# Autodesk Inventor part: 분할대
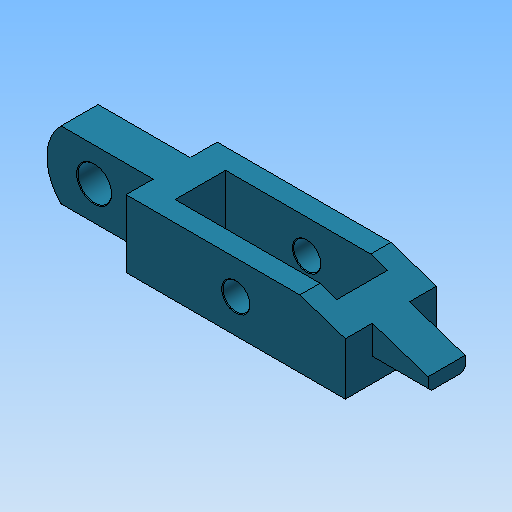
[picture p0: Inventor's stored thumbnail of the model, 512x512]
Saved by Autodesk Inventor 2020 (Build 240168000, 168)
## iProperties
Created: 2016-11
Part Number: 분할대
Material: 강철, 연강
Document SubType Name: Modeling
Designer: mduedu
Density: 1 g/cm^3
Appearance: 터키옥색
Author: mduedu
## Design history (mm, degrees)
sketch "스케치1"
  geometry: L1 (32.5, 13.5)-(-32.5, 13.5); L2 (-32.5, 13.5)-(-32.5, -13.5); L3 (-32.5, -13.5)-(32.5, -13.5); L4 (32.5, -13.5)-(32.5, 13.5); L5 (24, 7.5)-(-24, 7.5); L6 (-24, 7.5)-(-24, -7.5); L7 (-24, -7.5)-(24, -7.5); L8 (24, -7.5)-(24, 7.5); L9 (24, 0)-(-24, 0); L10 (0, -13.5)-(0, 13.5); 4 further points
  constraints: 20 end point, 7 midpoint, 4 parallel, 2 coincident, 2 horizontal, 2 perpendicular, 1 horizontal alignment
  dimensions: "d0" = 15 distance of L5.end L6.end; "d2" = 27 distance between parallel lines of L1 L3; "d3" = 48 distance of L5.start L5.end; "d4" = 65 distance of L1.start L1.end
extrude "돌출1" new body sketch "스케치1" distance "d5" = 20; taper "d6" = 0 deg
sketch "스케치2"
  geometry: L1 (0, 0)-(65, 0) reference; L2 (65, 0)-(65, 20) reference; L3 (0, 20)-(65, 20) reference; L4 (0, 0)-(0, 20) reference; L5 (32.5, 0)-(32.5, 20); C1 r 4 at (32.5, 10)
  constraints: 2 end point, 2 midpoint, 1 centre point
  dimensions: "d7" = 8 diameter of C1
extrude "돌출2" cut sketch "스케치2" extent not by distance; stored distance "d8" = 20; taper "d9" = 0 deg
chamfer "모따기1" distance "d10" = 0.2; stored, may be unused: second distance "d11" = 2, angle "d12" = 45 deg
sketch "스케치3"
  geometry: L1 (-32.5, 0)-(-32.5, 20) reference; L2 (-32.5, 20)-(-59.798, 20); L3 (-64, 20)-(-64, 0); L4 (-64, 0)-(-59.798, 0); L5 (-32.5, 0)-(-32.5, 20); L6 (-59.798, 20)-(-64, 20); L7 (-59.798, 0)-(-32.5, 0); C1 r 4.2 at (0, 10) reference; C2 r 5 at (-50, 10); A1 r 14 centre (-50, 10) between (-59.798, 20) and (-59.798, 0); 1 further point
  constraints: 12 end point, 5 parallel, 2 centre point, 2 horizontal, 2 perpendicular, 2 point on circle, 1 coincident, 1 horizontal alignment, 1 tangent
  dimensions: "d13" = 64 distance from line of L3 C1.centre; "d14" = 14 radius of A1; "d15" = 10 diameter of C2
extrude "돌출3" join sketch "스케치3" stored distance "d16" = 11; taper "d17" = 0 deg
sketch "스케치4"
  geometry: L1 (32.5, 0)-(32.5, 20) reference; L2 (32.5, 20)-(49, 20); L3 (49, 20)-(49, 6); L4 (49, 6)-(32.5, 6); L5 (32.5, 6)-(32.5, 20); L6 (32.5, 0)-(-32.5, 0) reference; 1 further point
  constraints: 8 end point, 2 parallel, 1 horizontal, 1 perpendicular
  dimensions: "d18" = 16.5 distance of L1.end L2.end; "d19" = 6 distance between parallel lines of L4 L6
extrude "돌출4" join sketch "스케치4" stored distance "d20" = 11; taper "d21" = 0 deg
chamfer "모따기2" distance "d22" = 30; stored, may be unused: second distance "d23" = 10, angle "d24" = 45 deg
chamfer "모따기3" distance "d25" = 1; stored, may be unused: second distance "d26" = 10, angle "d27" = 45 deg
chamfer "모따기4" distance "d28" = 0.2; stored, may be unused: second distance "d29" = 10, angle "d30" = 45 deg
node "솔리드1"
node "투영된 루프1"
